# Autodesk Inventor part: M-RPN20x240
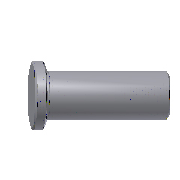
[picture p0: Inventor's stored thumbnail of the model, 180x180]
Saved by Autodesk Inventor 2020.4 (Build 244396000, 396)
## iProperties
Created: 2019-01
Part Number: M-RPN20x240
Material: SUJ 2
Description: Return Pin
Document SubType Name: Modeling
Designer: mel
Standard Revision: 1
Manufacturer: FUTABA
Language: fr-FR
Size Designation: 20x240
Categories: <MemberInstance><Categories><Category DisplayName="Moule" InternalName="349578f2-f4d4-4954-8c09-8e99297a61c0" Mnemonic="MOLD"><Category DisplayName="Composants
Mass: 6.63789 g
Surface Area: 25.7048 cm^2
Volume: 6.63789 cm^3
Density: 7.85 g/cm^3
Appearance: Aluminium - Noir
IsCustomPart: 1
Author: mel
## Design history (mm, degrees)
sketch "Sketch1"
  geometry: L1 (0, -15)-(0, 62) reference; L2 (0, -4)-(12.5, -4); L3 (12.5, -4)-(12.5, 0); L4 (12.5, 0)-(10, 0); L5 (10, 0)-(10, 236); L6 (10, 236)-(0, 236); L7 (0, 236)-(0, -4); 1 further point
  constraints: 12 end point, 3 perpendicular, 2 parallel, 2 point on line, 1 collinear, 1 horizontal alignment
  dimensions: "d28" = 4 distance between parallel lines of L2 L4 (= H_); "d29" = 25 diameter of L3 L1 (= D); "d31" = 20 diameter of L5 L1 (= d_); "d33" = 240 distance between parallel lines of L2 L6 (= L)
revolve "Revolution1" sketch "Sketch1" stored, may be unused: angle "d41" = 90 deg
sketch "Sketch2" dims "d31" = 20 (= d_)
  geometry: L1 (10, 236)-(10, 0) reference; L2 (-10, 0)-(10, 0) reference; L3 (10, 0)-(9.8, 0); L4 (9.5, 0.3)-(9.5, 0.9); L5 (9.8, 1.2)-(10, 1.2); L6 (10, 1.2)-(10, 0); L7 (0, -10.275)-(0, 61.212) reference; A1 r 0.3 centre (9.8, 0.9) between (9.8, 1.2) and (9.5, 0.9); A2 r 0.3 centre (9.8, 0.3) between (9.5, 0.3) and (9.8, 0); 1 further point
  constraints: 8 end point, 4 point on circle, 4 tangent, 2 centre point, 2 parallel, 1 equal radius, 1 horizontal, 1 perpendicular
  dimensions: "d45" = 0.3 radius of A1; "d46" = 1.2 distance between parallel lines of L2 L5; "d47" = 0.5 distance between parallel lines of L4 L1
revolve "Revolution2" sketch "Sketch2" stored, may be unused: angle "d48" = 90 deg
chamfer "Chamfer1" distance "d49" = 0.5; stored, may be unused: second distance "d50" = 2, angle "d51" = 45 deg
body "Solid1"
other parameters: "d_" = 20 [user parameter; used in 1 equation term], "L" = 240 [user parameter; used in 1 equation term], "D" = 25 [user parameter; used in 1 equation term], "H_" = 4 [user parameter; used in 1 equation term], "d44" = 0, "d52" = 0, "d53" = 0
